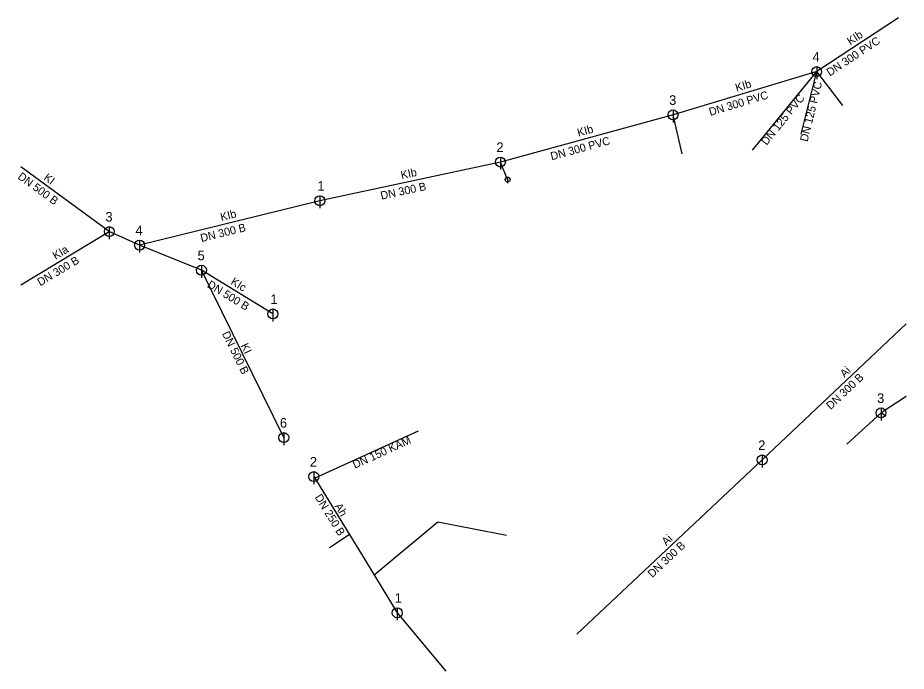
# Model space of a CAD drawing. Extents: x -446989 to -446811, y -1113341 to -1113210.
import ezdxf

# ---------------------------------------------------------------- set-up
doc = ezdxf.new("R2010")
doc.units = 0
for name, color, linetype in [('_pripojka_kanal_jednotna_prevzato_z_dokumentace_', 7, 'Continuous'), ('_pripojka_kanal_jednotna_priblizne_', 7, 'Continuous'), ('_stoka_jednotna_smvak_prevzato_z_dokumentace_', 7, 'Continuous'), ('Default', 7, 'Continuous'), ('MoLevel 119', 7, 'Continuous'), ('MoLevel 120', 7, 'Continuous'), ('MoLevel 124', 7, 'Continuous'), ('MoLevel 57', 7, 'Continuous'), ('MoLevel 68', 7, 'Continuous'), ('MoLevel 69', 7, 'Continuous')]:
    doc.layers.add(name, color=color, linetype=linetype)

# ---------------------------------------------------------------- blocks, each defined once
blk = doc.blocks.new('_sachta_kanal_prip_')
at = {"layer": 'Default'}
blk.add_line((0, 0.00005), (0, -0.000075), dxfattribs=at)
blk.add_circle((0, 0), 0.00005, dxfattribs=at)
blk = doc.blocks.new('_sachta_kanal_prevzato_z_dokumentace_')
at = {"layer": 'Default'}
blk.add_line((0, 0.00005), (0, -0.000075), dxfattribs=at)
blk.add_circle((0, 0), 0.00005, dxfattribs=at)

msp = doc.modelspace()

# ---------------------------------------------------------------- linework, layer by layer
at = {"layer": '_pripojka_kanal_jednotna_prevzato_z_dokumentace_'}
for p, q in [((-446891.11, -1113242.05), (-446892.57, -1113238.54)), ((-446815.25, -1113289.47), (-446816.24, -1113288.85))]:
    msp.add_line(p, q, dxfattribs=at)
at = {"layer": '_pripojka_kanal_jednotna_priblizne_'}
for p, q in [((-446841.98, -1113236.19), (-446829.14, -1113220.41)), ((-446832.23, -1113232.96), (-446829.14, -1113220.41)), ((-446823.9, -1113227.18), (-446829.14, -1113220.41)), ((-446856.09, -1113236.89), (-446857.94, -1113229.08)), ((-446909.06, -1113292.54), (-446929.79, -1113301.95)), ((-446926.84, -1113315.82), (-446922.87, -1113313.23))]:
    msp.add_line(p, q, dxfattribs=at)
msp.add_lwpolyline([(-446891.36, -1113313.45), (-446905.1, -1113310.77), (-446917.86, -1113321.41)], dxfattribs=at)
at = {"layer": '_stoka_jednotna_smvak_prevzato_z_dokumentace_'}
for p, q in [((-446812.76, -1113209.61), (-446829.14, -1113220.41)), ((-446829.14, -1113220.41), (-446857.94, -1113229.08)), ((-446857.94, -1113229.08), (-446892.57, -1113238.54)), ((-446970.98, -1113252.49), (-446988.75, -1113239.51)), ((-446892.57, -1113238.54), (-446928.77, -1113246.3)), ((-446928.77, -1113246.3), (-446964.91, -1113255.21)), ((-446988.75, -1113263.16), (-446970.98, -1113252.49)), ((-446964.91, -1113255.21), (-446970.98, -1113252.49)), ((-446952.51, -1113260.24), (-446964.91, -1113255.21)), ((-446936, -1113293.8), (-446952.51, -1113260.24)), ((-446938.18, -1113269.01), (-446952.51, -1113260.24)), ((-446811.18, -1113270.96), (-446840.08, -1113298.28)), ((-446811.18, -1113285.58), (-446816.24, -1113288.85)), ((-446816.24, -1113288.85), (-446823.06, -1113295.12)), ((-446840.08, -1113298.28), (-446877.26, -1113333.23)), ((-446913.25, -1113328.93), (-446903.49, -1113340.65))]:
    msp.add_line(p, q, dxfattribs=at)
msp.add_lwpolyline([(-446929.99, -1113301.62), (-446920.44, -1113317.2), (-446913.25, -1113328.93)], dxfattribs=at)

# ---------------------------------------------------------------- block references
at = {"layer": 'MoLevel 119', "xscale": 20000, "yscale": 20000}
for p in [(-446829.14, -1113220.41), (-446857.94, -1113229.08), (-446892.57, -1113238.54), (-446928.77, -1113246.3), (-446970.98, -1113252.49), (-446964.91, -1113255.21), (-446952.51, -1113260.24), (-446938.18, -1113269.01), (-446816.24, -1113288.85), (-446936, -1113293.8), (-446840.08, -1113298.28), (-446929.99, -1113301.62), (-446913.25, -1113328.93)]:
    msp.add_blockref('_sachta_kanal_prevzato_z_dokumentace_', p, dxfattribs=at)
at = {"layer": 'MoLevel 57', "xscale": 10000, "yscale": 10000}
msp.add_blockref('_sachta_kanal_prip_', (-446891.11, -1113242.05), dxfattribs=at)

# ---------------------------------------------------------------- texts
at = {"layer": 'MoLevel 120'}
for s, p in [('4', (-446829.97, -1113218.41)), ('3', (-446858.72, -1113227.08)), ('2', (-446893.35, -1113236.54)), ('1', (-446929.27, -1113244.3)), ('3', (-446971.76, -1113250.49)), ('4', (-446965.74, -1113253.21)), ('5', (-446953.29, -1113258.24)), ('1', (-446938.68, -1113267.01)), ('3', (-446817.02, -1113286.85)), ('6', (-446936.78, -1113291.8)), ('2', (-446840.86, -1113296.28)), ('2', (-446930.77, -1113299.62)), ('1', (-446913.75, -1113326.93))]:
    msp.add_text(s, height=1.93, dxfattribs=at).set_placement(p)
at = {"layer": 'MoLevel 124'}
for s, rotation, p in [('DN 125 PVC', 76.181, (-446830.97, -1113234.56)), ('DN 125 PVC', 50.858, (-446839.19, -1113235.3)), ('DN 150 KAM', 24.4183, (-446921.74, -1113300.06))]:
    msp.add_text(s, height=1.605, rotation=rotation, dxfattribs=at).set_placement(p)
at = {"layer": 'MoLevel 68'}
for s, rotation, p in [('DN 300 PVC', 33.3985, (-446826.51, -1113221.4)), ('DN 300 PVC', 16.754, (-446850.47, -1113229.31)), ('DN 300 PVC', 15.2789, (-446882.28, -1113238.19)), ('DN 500 B', 323.8504, (-446989.48, -1113241.76)), ('DN 300 B', 12.0991, (-446916.42, -1113246.09)), ('DN 300 B', 13.8496, (-446952.5, -1113254.6)), ('DN 300 B', 30.9818, (-446984.83, -1113263.48)), ('DN 500 B', 328.5333, (-446951.5, -1113263.54)), ('DN 500 B', 296.1951, (-446948.44, -1113272.94)), ('DN 300 B', 43.3967, (-446826.33, -1113288.29)), ('DN 250 B', 301.5063, (-446929.84, -1113305.74)), ('DN 300 B', 43.2292, (-446862.11, -1113321.99))]:
    msp.add_text(s, height=1.605, rotation=rotation, dxfattribs=at).set_placement(p)
at = {"layer": 'MoLevel 69'}
for s, rotation, p in [('KIb', 33.3985, (-446822.39, -1113215.16)), ('KIb', 16.754, (-446845.19, -1113224.44)), ('KIb', 15.2789, (-446876.91, -1113233.46)), ('KI', 323.8504, (-446984.28, -1113241.98)), ('KIb', 12.0991, (-446912.35, -1113241.98)), ('KIb', 13.8496, (-446948.51, -1113250.37)), ('KIa', 30.9818, (-446981.76, -1113258.16)), ('KIc', 328.5333, (-446946.78, -1113262.95)), ('KI', 296.1951, (-446944.68, -1113275.36)), ('Ai', 43.3967, (-446823.55, -1113281.85)), ('Ah', 301.5063, (-446925.87, -1113307.54)), ('Ai', 43.2292, (-446859.31, -1113315.56))]:
    msp.add_text(s, height=1.605, rotation=rotation, dxfattribs=at).set_placement(p)

doc.saveas('drawing.dxf')
